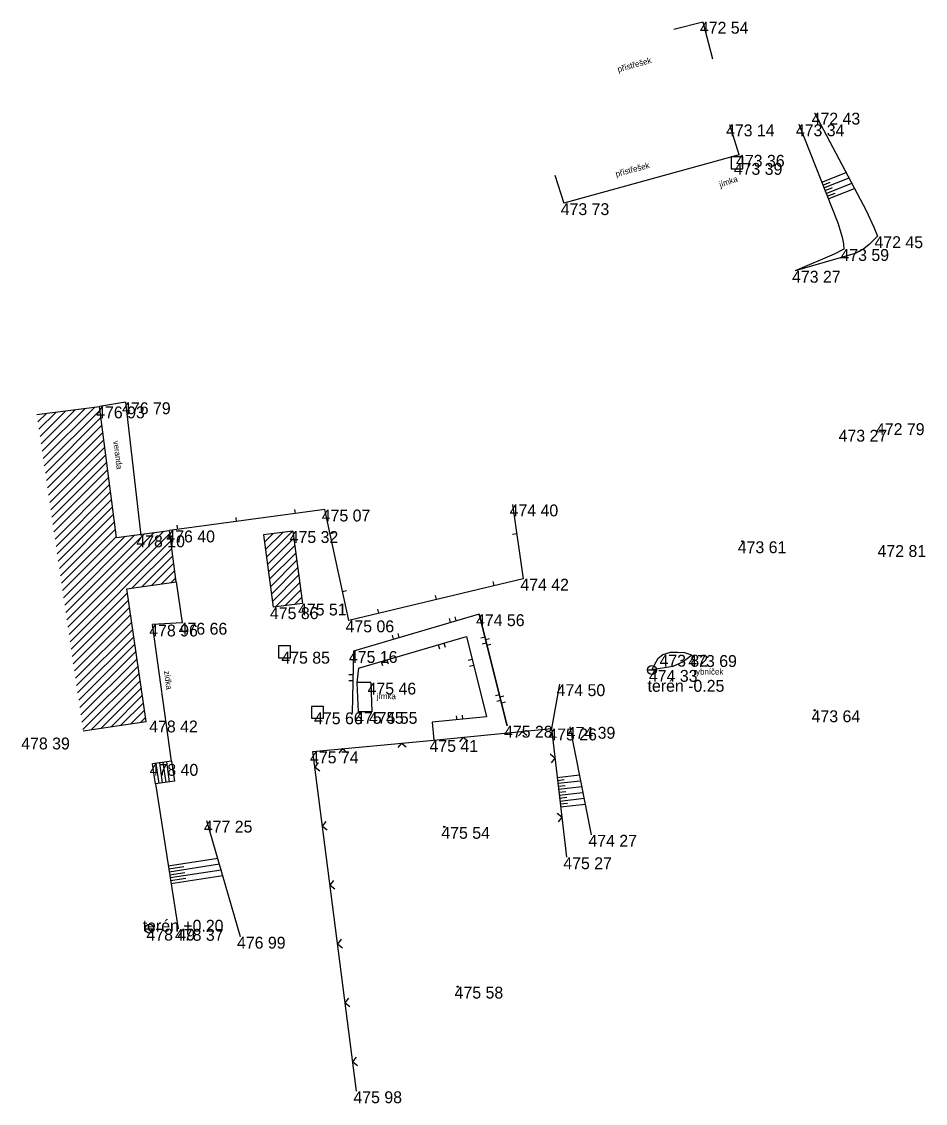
# Model space of a CAD drawing. Extents: x -553731 to -553573, y -1076100 to -1075378.
# Drawn here: x -553730.6 to -553654.5, y -1075975.3 to -1075884.2 of the extents above; entities that cross this region are included whole.
import ezdxf

# ---------------------------------------------------------------- set-up
doc = ezdxf.new("R2010")
doc.units = 0
for name, color, linetype in [('1', 7, 'Continuous'), ('12', 7, 'Continuous'), ('14', 7, 'Continuous'), ('18', 7, 'Continuous'), ('26', 7, 'Continuous'), ('27', 7, 'Continuous'), ('28', 7, 'Continuous'), ('32', 7, 'Continuous'), ('50', 7, 'Continuous'), ('52', 7, 'Continuous'), ('6', 7, 'Continuous')]:
    doc.layers.add(name, color=color, linetype=linetype)

# ---------------------------------------------------------------- blocks, each defined once
blk = doc.blocks.new('POINT_DISPLAY')
blk.add_line((0, 0), (0, 0))
blk = doc.blocks.new('SA')
at = {"layer": '50'}
blk.add_lwpolyline([(-0.5, -0.5), (0.5, -0.5), (0.5, 0.5), (-0.5, 0.5)], close=True, dxfattribs=at)
blk = doc.blocks.new('T')
at = {"layer": '6'}
blk.add_circle((0, 0), 0.05, dxfattribs=at)
blk = doc.blocks.new('ST')
at = {"layer": '1'}
blk.add_line((-0.375, 0), (0.375, 0), dxfattribs=at)
blk.add_circle((0, 0), 0.375, dxfattribs=at)

msp = doc.modelspace()

# ---------------------------------------------------------------- linework, layer by layer
at = {"layer": '12'}
for p, q in [((-553689.22, -1075924.85), (-553688.32, -1075931.1)), ((-553705.02, -1075925.28), (-553718.1, -1075927.04)), ((-553712.453, -1075926.28), (-553712.5, -1075925.933)), ((-553707.498, -1075925.613), (-553707.544, -1075925.267)), ((-553703, -1075934.61), (-553705.02, -1075925.28)), ((-553717.408, -1075926.947), (-553717.455, -1075926.6)), ((-553704.587, -1075927.28), (-553704.245, -1075927.206)), ((-553688.864, -1075927.324), (-553689.21, -1075927.374)), ((-553688.32, -1075931.1), (-553703, -1075934.61)), ((-553690.751, -1075931.681), (-553690.833, -1075931.341)), ((-553703.529, -1075932.167), (-553703.187, -1075932.093)), ((-553695.614, -1075932.844), (-553695.696, -1075932.504)), ((-553692.03, -1075934.09), (-553702.61, -1075937.19)), ((-553700.477, -1075934.007), (-553700.559, -1075933.666)), ((-553692.03, -1075934.09), (-553689.67, -1075943.48)), ((-553689.67, -1075943.48), (-553692.03, -1075934.09)), ((-553694.429, -1075934.793), (-553694.528, -1075934.457)), ((-553693.949, -1075934.652), (-553694.048, -1075934.316)), ((-553702.188, -1075938.629), (-553693.104, -1075935.967)), ((-553699.227, -1075936.199), (-553699.326, -1075935.863)), ((-553698.748, -1075936.058), (-553698.846, -1075935.722)), ((-553693.104, -1075935.967), (-553691.402, -1075942.738)), ((-553691.542, -1075936.03), (-553691.882, -1075936.115)), ((-553695.47, -1075936.66), (-553695.372, -1075936.996)), ((-553694.991, -1075936.52), (-553694.892, -1075936.856)), ((-553691.421, -1075936.515), (-553691.76, -1075936.6)), ((-553691.498, -1075936.206), (-553691.159, -1075936.121)), ((-553691.376, -1075936.691), (-553691.037, -1075936.606)), ((-553702.61, -1075937.19), (-553702.715, -1075942.426)), ((-553692.616, -1075937.907), (-553692.956, -1075937.992)), ((-553702.188, -1075938.629), (-553702.33, -1075939.85)), ((-553700.269, -1075938.067), (-553700.17, -1075938.402)), ((-553699.789, -1075937.926), (-553699.69, -1075938.262)), ((-553692.495, -1075938.392), (-553692.834, -1075938.477)), ((-553702.66, -1075939.689), (-553703.01, -1075939.682)), ((-553702.65, -1075939.19), (-553703, -1075939.183)), ((-553690.324, -1075940.879), (-553690.663, -1075940.964)), ((-553690.202, -1075941.364), (-553690.541, -1075941.449)), ((-553690.279, -1075941.055), (-553689.94, -1075940.97)), ((-553690.158, -1075941.54), (-553689.818, -1075941.455)), ((-553691.402, -1075942.738), (-553695.995, -1075943.187)), ((-553695.995, -1075943.187), (-553695.85, -1075944.68)), ((-553693.89, -1075942.981), (-553693.924, -1075942.633)), ((-553693.393, -1075942.933), (-553693.427, -1075942.584)), ((-553695.85, -1075944.68), (-553685.93, -1075943.71)), ((-553688.386, -1075943.95), (-553688.703, -1075944.337)), ((-553688.386, -1075943.95), (-553687.999, -1075944.268)), ((-553685.93, -1075943.71), (-553684.68, -1075954.55)), ((-553706.02, -1075945.64), (-553695.85, -1075944.68)), ((-553698.553, -1075944.935), (-553698.872, -1075945.321)), ((-553698.553, -1075944.935), (-553698.167, -1075945.254)), ((-553693.362, -1075944.437), (-553693.68, -1075944.823)), ((-553693.362, -1075944.437), (-553692.975, -1075944.755)), ((-553702.34, -1075974.25), (-553706.02, -1075945.64)), ((-553703.531, -1075945.405), (-553703.85, -1075945.791)), ((-553703.531, -1075945.405), (-553703.145, -1075945.724)), ((-553685.644, -1075946.194), (-553686.036, -1075945.882)), ((-553705.848, -1075946.975), (-553705.542, -1075946.578)), ((-553705.848, -1075946.975), (-553705.452, -1075947.281)), ((-553685.644, -1075946.194), (-553685.955, -1075946.586)), ((-553705.21, -1075951.934), (-553704.904, -1075951.538)), ((-553685.071, -1075951.161), (-553685.463, -1075950.85)), ((-553685.071, -1075951.161), (-553685.382, -1075951.553)), ((-553705.21, -1075951.934), (-553704.814, -1075952.24)), ((-553704.573, -1075956.893), (-553704.267, -1075956.497)), ((-553704.573, -1075956.893), (-553704.176, -1075957.199)), ((-553703.935, -1075961.852), (-553703.629, -1075961.456)), ((-553703.935, -1075961.852), (-553703.538, -1075962.158)), ((-553703.297, -1075966.811), (-553702.991, -1075966.415)), ((-553703.297, -1075966.811), (-553702.901, -1075967.117)), ((-553702.659, -1075971.77), (-553702.353, -1075971.374)), ((-553702.659, -1075971.77), (-553702.263, -1075972.076))]:
    msp.add_line(p, q, dxfattribs=at)
at = {"layer": '14'}
for p, q in [((-553675.63, -1075884.851), (-553673.19, -1075884.22)), ((-553673.19, -1075884.22), (-553672.38, -1075887.35)), ((-553670.12, -1075895.42), (-553670.92, -1075892.89)), ((-553670.12, -1075895.42), (-553684.9, -1075899.49)), ((-553685.65, -1075897.12), (-553684.9, -1075899.49)), ((-553729.275, -1075917.285), (-553723.99, -1075916.6)), ((-553721.81, -1075916.25), (-553723.99, -1075916.6)), ((-553722.562, -1075927.618), (-553723.99, -1075916.6)), ((-553721.81, -1075916.25), (-553720.52, -1075927.45)), ((-553722.562, -1075927.618), (-553718.1, -1075927.04)), ((-553717.54, -1075931.36), (-553718.1, -1075927.04)), ((-553707.72, -1075927.09), (-553710.18, -1075927.4)), ((-553710.18, -1075927.4), (-553709.37, -1075933.5)), ((-553707.72, -1075927.09), (-553706.91, -1075933.19)), ((-553721.684, -1075931.958), (-553717.54, -1075931.36)), ((-553720.074, -1075943.116), (-553721.684, -1075931.958)), ((-553706.91, -1075933.19), (-553709.37, -1075933.5)), ((-553725.371, -1075943.906), (-553720.074, -1075943.116))]:
    msp.add_line(p, q, dxfattribs=at)
at = {"layer": '18'}
for p, q in [((-553717.54, -1075931.36), (-553717.03, -1075934.81)), ((-553717.03, -1075934.81), (-553719.52, -1075934.96)), ((-553717.921, -1075946.459), (-553719.52, -1075934.96)), ((-553702.33, -1075939.85), (-553702.22, -1075942.31)), ((-553701.16, -1075939.85), (-553702.33, -1075939.85)), ((-553701.16, -1075939.85), (-553701.05, -1075942.31)), ((-553701.05, -1075942.31), (-553702.22, -1075942.31)), ((-553717.921, -1075946.459), (-553719.52, -1075946.69)), ((-553719.277, -1075948.373), (-553719.52, -1075946.69)), ((-553718.98, -1075948.33), (-553719.223, -1075946.647)), ((-553718.683, -1075948.287), (-553718.926, -1075946.604)), ((-553718.386, -1075948.244), (-553718.629, -1075946.561)), ((-553718.089, -1075948.201), (-553718.332, -1075946.518)), ((-553717.921, -1075946.459), (-553717.678, -1075948.142)), ((-553717.678, -1075948.142), (-553719.277, -1075948.373)), ((-553719.277, -1075948.373), (-553717.38, -1075960.58))]:
    msp.add_line(p, q, dxfattribs=at)
at = {"layer": '26'}
for p, q in [((-553663.178, -1075897.729), (-553661.117, -1075896.913)), ((-553663.086, -1075897.962), (-553662.46, -1075897.714)), ((-553662.994, -1075898.194), (-553660.882, -1075897.358)), ((-553662.81, -1075898.659), (-553660.647, -1075897.803)), ((-553662.902, -1075898.427), (-553662.261, -1075898.173)), ((-553662.718, -1075898.892), (-553662.061, -1075898.632)), ((-553662.626, -1075899.124), (-553660.412, -1075898.248)), ((-553685.455, -1075947.825), (-553683.586, -1075947.609)), ((-553685.427, -1075948.074), (-553684.86, -1075948.008)), ((-553685.398, -1075948.322), (-553683.488, -1075948.102)), ((-553685.37, -1075948.571), (-553684.79, -1075948.504)), ((-553685.341, -1075948.819), (-553683.39, -1075948.594)), ((-553685.312, -1075949.067), (-553684.721, -1075948.999)), ((-553685.284, -1075949.316), (-553683.292, -1075949.086)), ((-553685.255, -1075949.564), (-553684.651, -1075949.494)), ((-553685.226, -1075949.812), (-553683.194, -1075949.578)), ((-553685.198, -1075950.061), (-553684.582, -1075949.99)), ((-553685.169, -1075950.309), (-553683.096, -1075950.07)), ((-553718.204, -1075955.277), (-553714.035, -1075954.629)), ((-553718.127, -1075955.771), (-553713.895, -1075955.113)), ((-553718.166, -1075955.524), (-553716.906, -1075955.328)), ((-553718.089, -1075956.018), (-553716.81, -1075955.819)), ((-553718.051, -1075956.265), (-553713.755, -1075955.597)), ((-553717.974, -1075956.759), (-553713.614, -1075956.081)), ((-553718.012, -1075956.512), (-553716.714, -1075956.31))]:
    msp.add_line(p, q, dxfattribs=at)
at = {"layer": '27'}
for p, q in [((-553685.25, -1075939.98), (-553685.93, -1075943.71)), ((-553684.39, -1075943.57), (-553682.58, -1075952.66)), ((-553712.12, -1075961.24), (-553714.95, -1075951.47))]:
    msp.add_line(p, q, dxfattribs=at)
for points in [[(-553663.78, -1075891.87), (-553659.432, -1075900.103), (-553658.789, -1075901.497), (-553658.49, -1075902.27)], [(-553665.11, -1075892.85), (-553661.829, -1075901.138), (-553661.456, -1075902.353), (-553661.346, -1075902.905), (-553661.33, -1075903.35)], [(-553658.49, -1075902.27), (-553659.184, -1075902.974), (-553659.646, -1075903.319), (-553660.372, -1075903.72), (-553665.42, -1075905.18)], [(-553661.33, -1075903.35), (-553662.133, -1075903.775), (-553665.42, -1075905.18)]]:
    msp.add_lwpolyline(points, dxfattribs=at)
at = {"layer": '28'}
for points in [[(-553677.48, -1075938.78), (-553676.963, -1075937.798), (-553676.58, -1075937.5)], [(-553674.13, -1075937.53), (-553674.854, -1075938.109), (-553675.717, -1075938.493), (-553677.48, -1075938.78)], [(-553674.13, -1075937.53), (-553674.71, -1075937.331), (-553675.321, -1075937.319), (-553675.932, -1075937.319), (-553676.58, -1075937.5)]]:
    msp.add_lwpolyline(points, dxfattribs=at)
at = {"layer": '32'}
for p, q in [((-553729.004, -1075919.135), (-553726.838, -1075916.969)), ((-553728.913, -1075919.752), (-553726.025, -1075916.864)), ((-553728.823, -1075920.368), (-553725.213, -1075916.759)), ((-553728.732, -1075920.985), (-553724.401, -1075916.653)), ((-553728.642, -1075921.602), (-553723.95, -1075916.91)), ((-553729.185, -1075917.902), (-553728.463, -1075917.18)), ((-553729.094, -1075918.518), (-553727.65, -1075917.074)), ((-553728.552, -1075922.218), (-553723.869, -1075917.536)), ((-553728.461, -1075922.835), (-553723.788, -1075918.162)), ((-553728.371, -1075923.452), (-553723.706, -1075918.788)), ((-553728.28, -1075924.068), (-553723.625, -1075919.414)), ((-553728.19, -1075924.685), (-553723.544, -1075920.04)), ((-553728.099, -1075925.302), (-553723.463, -1075920.665)), ((-553728.009, -1075925.918), (-553723.382, -1075921.291)), ((-553727.918, -1075926.535), (-553723.301, -1075921.917)), ((-553727.828, -1075927.152), (-553723.22, -1075922.543)), ((-553727.738, -1075927.768), (-553723.139, -1075923.169)), ((-553727.647, -1075928.385), (-553723.057, -1075923.795)), ((-553727.557, -1075929.002), (-553722.976, -1075924.421)), ((-553727.466, -1075929.618), (-553722.895, -1075925.047)), ((-553727.376, -1075930.235), (-553722.814, -1075925.673)), ((-553727.285, -1075930.852), (-553722.733, -1075926.299)), ((-553727.195, -1075931.468), (-553722.652, -1075926.925)), ((-553727.105, -1075932.085), (-553722.571, -1075927.551)), ((-553727.014, -1075932.702), (-553721.836, -1075927.524)), ((-553726.924, -1075933.318), (-553721.024, -1075927.419)), ((-553726.833, -1075933.935), (-553720.212, -1075927.314)), ((-553726.743, -1075934.552), (-553719.399, -1075927.208)), ((-553726.652, -1075935.168), (-553718.587, -1075927.103)), ((-553726.562, -1075935.785), (-553718.068, -1075927.291)), ((-553710.097, -1075928.024), (-553709.371, -1075927.298)), ((-553710.014, -1075928.648), (-553708.562, -1075927.196)), ((-553709.931, -1075929.273), (-553707.753, -1075927.094)), ((-553709.848, -1075929.897), (-553707.64, -1075927.689)), ((-553726.471, -1075936.402), (-553717.986, -1075927.917)), ((-553721.259, -1075931.897), (-553717.905, -1075928.543)), ((-553709.766, -1075930.521), (-553707.558, -1075928.313)), ((-553720.433, -1075931.777), (-553717.824, -1075929.169)), ((-553709.683, -1075931.145), (-553707.475, -1075928.937)), ((-553709.6, -1075931.77), (-553707.392, -1075929.562)), ((-553719.607, -1075931.658), (-553717.743, -1075929.795)), ((-553718.78, -1075931.539), (-553717.662, -1075930.421)), ((-553709.517, -1075932.394), (-553707.309, -1075930.186)), ((-553717.954, -1075931.42), (-553717.581, -1075931.046)), ((-553709.434, -1075933.018), (-553707.226, -1075930.81)), ((-553709.186, -1075933.477), (-553707.143, -1075931.434)), ((-553726.381, -1075937.018), (-553721.638, -1075932.276)), ((-553708.377, -1075933.375), (-553707.06, -1075932.058)), ((-553726.291, -1075937.635), (-553721.549, -1075932.894)), ((-553707.568, -1075933.273), (-553706.977, -1075932.683)), ((-553726.2, -1075938.252), (-553721.46, -1075933.511)), ((-553726.11, -1075938.868), (-553721.371, -1075934.129)), ((-553726.019, -1075939.485), (-553721.282, -1075934.747)), ((-553725.929, -1075940.102), (-553721.192, -1075935.365)), ((-553725.838, -1075940.719), (-553721.103, -1075935.983)), ((-553725.748, -1075941.335), (-553721.014, -1075936.601)), ((-553725.658, -1075941.952), (-553720.925, -1075937.219)), ((-553725.567, -1075942.569), (-553720.836, -1075937.837)), ((-553725.477, -1075943.185), (-553720.747, -1075938.455)), ((-553725.386, -1075943.802), (-553720.657, -1075939.073)), ((-553724.68, -1075943.803), (-553720.568, -1075939.691)), ((-553723.849, -1075943.679), (-553720.479, -1075940.309)), ((-553723.018, -1075943.555), (-553720.39, -1075940.927)), ((-553722.187, -1075943.431), (-553720.301, -1075941.545)), ((-553721.356, -1075943.307), (-553720.212, -1075942.163)), ((-553720.525, -1075943.183), (-553720.122, -1075942.781))]:
    msp.add_line(p, q, dxfattribs=at)

# ---------------------------------------------------------------- block references
at = {"layer": '1'}
for name, p in [('POINT_DISPLAY', (-553673.19, -1075884.22)), ('POINT_DISPLAY', (-553663.78, -1075891.87)), ('POINT_DISPLAY', (-553670.88, -1075892.86)), ('POINT_DISPLAY', (-553665.11, -1075892.85)), ('POINT_DISPLAY', (-553670.12, -1075895.42)), ('POINT_DISPLAY', (-553670.31, -1075896.1)), ('POINT_DISPLAY', (-553684.9, -1075899.49)), ('POINT_DISPLAY', (-553658.49, -1075902.27)), ('POINT_DISPLAY', (-553661.33, -1075903.35)), ('POINT_DISPLAY', (-553665.42, -1075905.18)), ('POINT_DISPLAY', (-553723.99, -1075916.6)), ('POINT_DISPLAY', (-553721.81, -1075916.25)), ('POINT_DISPLAY', (-553661.5, -1075918.56)), ('POINT_DISPLAY', (-553658.34, -1075918.01)), ('POINT_DISPLAY', (-553689.22, -1075924.85)), ('POINT_DISPLAY', (-553705.02, -1075925.28)), ('POINT_DISPLAY', (-553720.52, -1075927.45)), ('POINT_DISPLAY', (-553718.1, -1075927.04)), ('POINT_DISPLAY', (-553707.72, -1075927.09)), ('POINT_DISPLAY', (-553669.87, -1075927.95)), ('POINT_DISPLAY', (-553658.11, -1075928.27)), ('POINT_DISPLAY', (-553717.54, -1075931.36)), ('POINT_DISPLAY', (-553688.32, -1075931.1)), ('POINT_DISPLAY', (-553706.91, -1075933.19)), ('POINT_DISPLAY', (-553709.37, -1075933.5)), ('POINT_DISPLAY', (-553692.03, -1075934.09)), ('POINT_DISPLAY', (-553719.52, -1075934.96)), ('POINT_DISPLAY', (-553717.03, -1075934.81)), ('POINT_DISPLAY', (-553703, -1075934.61)), ('POINT_DISPLAY', (-553708.42, -1075937.25)), ('POINT_DISPLAY', (-553702.61, -1075937.19)), ('POINT_DISPLAY', (-553676.58, -1075937.5)), ('POINT_DISPLAY', (-553674.13, -1075937.53)), ('ST', (-553677.48, -1075938.78)), ('POINT_DISPLAY', (-553677.48, -1075938.78)), ('POINT_DISPLAY', (-553701.16, -1075939.85)), ('POINT_DISPLAY', (-553685.25, -1075939.98)), ('POINT_DISPLAY', (-553705.64, -1075942.35)), ('POINT_DISPLAY', (-553702.22, -1075942.31)), ('POINT_DISPLAY', (-553701.05, -1075942.31)), ('POINT_DISPLAY', (-553663.77, -1075942.18)), ('POINT_DISPLAY', (-553719.56, -1075943.04)), ('POINT_DISPLAY', (-553689.67, -1075943.48)), ('POINT_DISPLAY', (-553685.93, -1075943.71)), ('POINT_DISPLAY', (-553684.39, -1075943.57)), ('POINT_DISPLAY', (-553730.31, -1075944.47)), ('POINT_DISPLAY', (-553695.85, -1075944.68)), ('POINT_DISPLAY', (-553706.02, -1075945.64)), ('POINT_DISPLAY', (-553719.52, -1075946.69)), ('POINT_DISPLAY', (-553714.95, -1075951.47)), ('POINT_DISPLAY', (-553694.96, -1075951.99)), ('POINT_DISPLAY', (-553682.58, -1075952.66)), ('POINT_DISPLAY', (-553684.68, -1075954.55)), ('ST', (-553719.78, -1075960.56)), ('POINT_DISPLAY', (-553719.78, -1075960.56)), ('POINT_DISPLAY', (-553717.38, -1075960.58)), ('POINT_DISPLAY', (-553712.12, -1075961.24)), ('POINT_DISPLAY', (-553693.83, -1075965.44)), ('POINT_DISPLAY', (-553702.34, -1075974.25))]:
    msp.add_blockref(name, p, dxfattribs=at)
at = {"layer": '32'}
for p in [(-553729.275, -1075917.285), (-553710.18, -1075927.4)]:
    msp.add_blockref('POINT_DISPLAY', p, dxfattribs=at)
at = {"layer": '50'}
for p in [(-553670.31, -1075896.1), (-553708.42, -1075937.25), (-553705.64, -1075942.35)]:
    msp.add_blockref('SA', p, dxfattribs=at)
at = {"layer": '6'}
for p in [(-553669.87, -1075927.95), (-553663.77, -1075942.18), (-553694.96, -1075951.99), (-553693.83, -1075965.44)]:
    msp.add_blockref('T', p, dxfattribs=at)

# ---------------------------------------------------------------- texts
at = {"layer": '52'}
for s, rotation, p in [('přístřešek', 16.02243, (-553680.298, -1075888.479)), ('přístřešek', 15.39607, (-553680.469, -1075897.285)), ('jímka', 19.53104, (-553671.712, -1075898.174)), ('veranda', 277.38472, (-553722.85, -1075919.513)), ('zídka', 277.91653, (-553718.577, -1075938.882))]:
    msp.add_text(s, height=0.5, rotation=rotation, dxfattribs=at).set_placement(p)
for s, p in [('rybníček', (-553673.986, -1075939.17)), ('jímka', (-553700.642, -1075941.239))]:
    msp.add_text(s, height=0.5, dxfattribs=at).set_placement(p)
at = {"layer": '6'}
for s, p in [('472 54 ', (-553673.438, -1075885.22)), ('472 43 ', (-553664.028, -1075892.87)), ('473 14 ', (-553671.237, -1075893.86)), ('473 34 ', (-553665.358, -1075893.85)), ('473 36 ', (-553670.392, -1075896.42)), ('473 39 ', (-553670.582, -1075897.1)), ('473 73 ', (-553685.158, -1075900.49)), ('472 45 ', (-553658.738, -1075903.27)), ('473 59 ', (-553661.602, -1075904.35)), ('473 27 ', (-553665.678, -1075906.18)), ('476 93 ', (-553724.274, -1075917.6)), ('476 79 ', (-553722.092, -1075917.25)), ('473 27 ', (-553661.758, -1075919.56)), ('472 79 ', (-553658.61, -1075919.01)), ('474 40 ', (-553689.458, -1075925.85)), ('475 07 ', (-553705.28, -1075926.28)), ('478 10 ', (-553720.891, -1075928.45)), ('476 40 ', (-553718.362, -1075928.04)), ('475 32 ', (-553707.98, -1075928.09)), ('473 61 ', (-553670.249, -1075928.95)), ('472 81 ', (-553658.477, -1075929.27)), ('474 42 ', (-553688.556, -1075932.1)), ('475 51 ', (-553707.277, -1075934.19)), ('475 86 ', (-553709.642, -1075934.5)), ('474 56 ', (-553692.29, -1075935.09)), ('478 96 ', (-553719.804, -1075935.96)), ('476 66 ', (-553717.326, -1075935.81)), ('475 06 ', (-553703.274, -1075935.61)), ('475 85 ', (-553708.68, -1075938.25)), ('475 16 ', (-553702.991, -1075938.19)), ('473 82 ', (-553676.84, -1075938.5)), ('473 69 ', (-553674.414, -1075938.53)), ('474 33 ', (-553677.728, -1075939.78)), ('terén -0.25', (-553677.845, -1075940.616)), ('475 46 ', (-553701.42, -1075940.85)), ('474 50 ', (-553685.5, -1075940.98)), ('475 66 ', (-553705.924, -1075943.35)), ('475 45 ', (-553702.468, -1075943.31)), ('475 55 ', (-553701.31, -1075943.31)), ('473 64 ', (-553664.03, -1075943.18)), ('478 42 ', (-553719.808, -1075944.04)), ('475 28 ', (-553689.93, -1075944.48)), ('475 26 ', (-553686.202, -1075944.71)), ('474 39 ', (-553684.65, -1075944.57)), ('478 39 ', (-553730.582, -1075945.47)), ('475 41 ', (-553696.205, -1075945.68)), ('475 74 ', (-553706.266, -1075946.64)), ('478 40 ', (-553719.77, -1075947.69)), ('477 25 ', (-553715.208, -1075952.47)), ('475 54 ', (-553695.208, -1075952.99)), ('474 27 ', (-553682.826, -1075953.66)), ('475 27 ', (-553684.938, -1075955.55)), ('terén +0.20', (-553720.357, -1075960.811)), ('478 49 ', (-553720.04, -1075961.56)), ('478 37 ', (-553717.638, -1075961.58)), ('476 99 ', (-553712.416, -1075962.24)), ('475 58 ', (-553694.09, -1075966.44)), ('475 98 ', (-553702.612, -1075975.25))]:
    msp.add_text(s, height=1, dxfattribs=at).set_placement(p)

doc.saveas('drawing.dxf')
